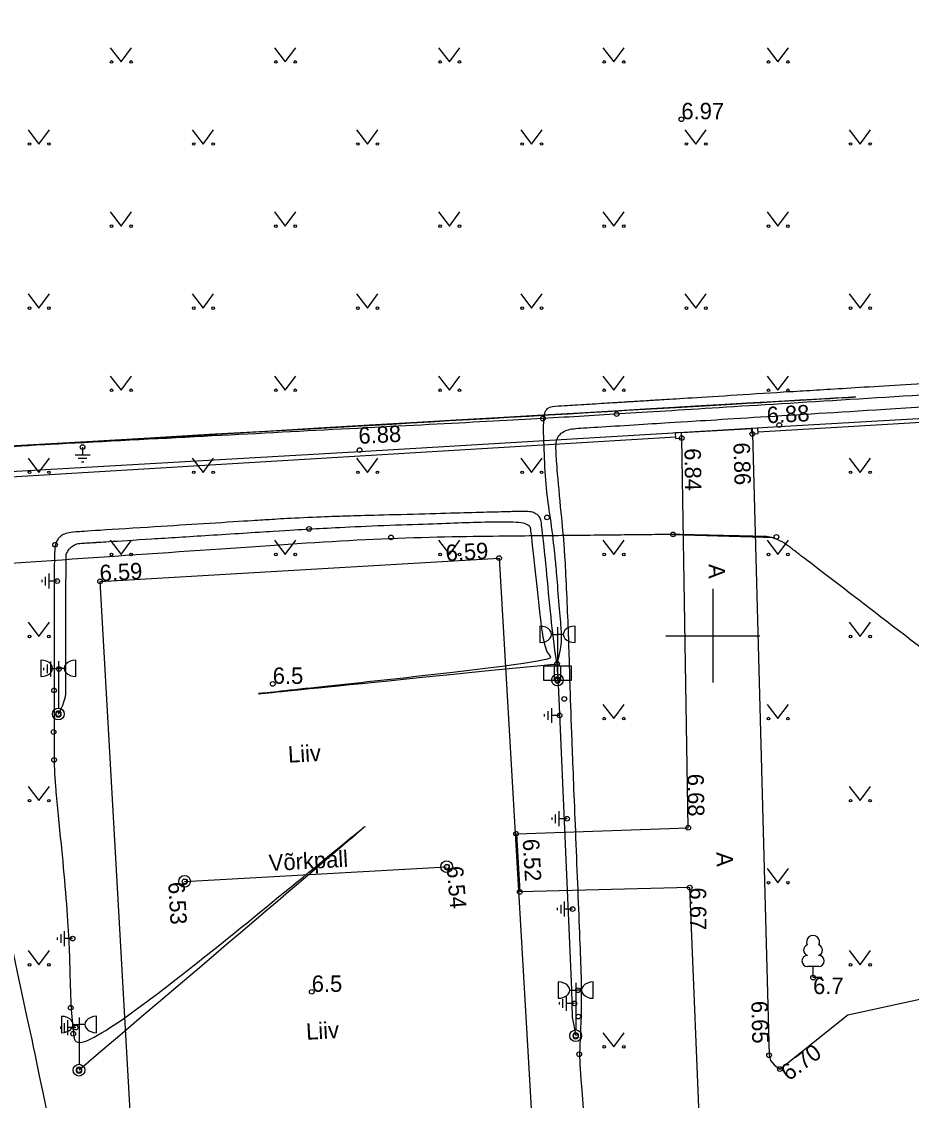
# Model space of a CAD drawing. Extents: x 473307 to 473719, y 6532843 to 6533381.
# Drawn here: x 473420.53 to 473458.46, y 6533180.18 to 6533226.19 of the extents above; entities that cross this region are included whole.
import ezdxf

# ---------------------------------------------------------------- set-up
doc = ezdxf.new("R2010")
doc.units = 0
for name, color, linetype in [('AED', 7, 'Continuous'), ('Default', 7, 'Continuous'), ('HALJASTUS', 7, 'Continuous'), ('KORGUS', 7, 'Continuous'), ('MPKAABEL', 7, 'Continuous'), ('POST', 7, 'Continuous'), ('PUU', 7, 'Continuous'), ('RAJATIS', 7, 'Continuous'), ('TEE', 7, 'Continuous'), ('VORK', 7, 'Continuous')]:
    doc.layers.add(name, color=color, linetype=linetype)

# ---------------------------------------------------------------- blocks, each defined once
blk = doc.blocks.new('VARPOS')
at = {"layer": 'Default'}
for p, q in [((-0.25, 0.25), (-0.25, -0.25)), ((-0.25, 0.25), (0.25, 0.25)), ((0.25, 0.25), (0.25, -0.25)), ((-0.25, -0.25), (0.25, -0.25))]:
    blk.add_line(p, q, dxfattribs=at)
blk = doc.blocks.new('ELKAPP')
at = {"layer": 'Default'}
for p, q in [((1.195, 0.597), (-1.195, 0.597)), ((-1.195, 0.597), (-1.195, -0.597)), ((-0.271, 0.597), (-0.271, -0.597)), ((0.271, 0.597), (0.271, -0.597)), ((1.195, -0.597), (1.195, 0.597)), ((-1.195, -0.597), (1.195, -0.597))]:
    blk.add_line(p, q, dxfattribs=at)
blk = doc.blocks.new('PRMAST')
at = {"layer": 'Default'}
for p, q in [((0, 4.5), (0, 0.5)), ((1.5, 3.193), (1.5, 4.593))]:
    blk.add_line(p, q, dxfattribs=at)
blk.add_lwpolyline([(0.5, 3.893), (0, 3.893)], dxfattribs=at)
blk.add_ellipse((1.5, 3.893), major_axis=(-1, 0), ratio=0.7, start_param=4.712389, end_param=7.853982, dxfattribs=at)
blk = doc.blocks.new('MEPOST')
at = {"layer": 'Default'}
blk.add_circle((0, 0), 0.5, dxfattribs=at)
for start, end in [(0, 180), (180, 0)]:
    blk.add_arc((0, 0), 0.25, start, end, dxfattribs=at)
blk = doc.blocks.new('MAANDU')
at = {"layer": 'Default'}
for points in [[(0, 0), (0, -0.678)], [(0.636, -0.678), (-0.636, -0.678)], [(0.368, -0.978), (-0.368, -0.978)], [(0.1, -1.278), (-0.1, -1.278)]]:
    blk.add_lwpolyline(points, dxfattribs=at)
blk = doc.blocks.new('LEHTP1')
at = {"layer": 'Default'}
for p, q in [((0.48, 0.95), (-0.48, 0.95)), ((0, 0), (0, 0.95)), ((0.76, 0), (0, 0))]:
    blk.add_line(p, q, dxfattribs=at)
for centre, radius, start, end in [((-0.34, 2.345), 0.465, 109.02174, 253.14154), ((0, 3.04), 0.554, 332.5799, 207.4201), ((0.34, 2.345), 0.465, 286.85082, 70.98591), ((-0.475, 1.425), 0.475, 90.0016, 269.3953), ((0.475, 1.425), 0.475, 270.6047, 89.9984)]:
    blk.add_arc(centre, radius, start, end, dxfattribs=at)
blk = doc.blocks.new('MURU')
at = {"layer": 'Default'}
for p, q in [((-0.927, 1.213), (0, 0)), ((0, 0), (0.891, 1.213))]:
    blk.add_line(p, q, dxfattribs=at)
for centre in [(-0.802, 0), (0.856, 0)]:
    blk.add_circle(centre, 0.11, dxfattribs=at)
blk = doc.blocks.new('VKORIS')
at = {"layer": 'Default'}
for p, q in [((0, 4), (0, -4)), ((-4, 0), (4, 0))]:
    blk.add_line(p, q, dxfattribs=at)
blk = doc.blocks.new('PLPOST')
at = {"layer": 'Default'}
blk.add_circle((0, 0), 0.5, dxfattribs=at)
blk.add_arc((0, 0), 0.25, 225, 45, dxfattribs=at)

msp = doc.modelspace()

# ---------------------------------------------------------------- linework, layer by layer
at = {"layer": 'AED'}
for points in [[(473499.831, 6533211.522), (473451.926, 6533208.685)], [(473399.054, 6533209.3), (473399.274, 6533205.529), (473448.417, 6533208.478)]]:
    msp.add_lwpolyline(points, dxfattribs=at)
at = {"layer": 'KORGUS'}
for centre in [(473448.657, 6533222.023), (473445.898, 6533209.449), (473442.754, 6533209.257), (473452.826, 6533208.98), (473448.67, 6533208.429), (473451.681, 6533208.606), (473423.132, 6533208.045), (473434.941, 6533207.916), (473442.932, 6533205.046), (473432.789, 6533204.555), (473448.301, 6533204.318), (473421.962, 6533203.88), (473436.282, 6533204.191), (473452.71, 6533204.217), (473440.889, 6533203.308), (473422.048, 6533202.329), (473423.879, 6533202.315), (473443.359, 6533198.806), (473422.122, 6533198.585), (473431.239, 6533197.948), (473443.373, 6533198.111), (473421.918, 6533197.668), (473443.664, 6533197.304), (473422.102, 6533196.661), (473443.467, 6533196.6), (473421.895, 6533195.895), (473421.918, 6533194.705), (473443.782, 6533192.197), (473448.948, 6533191.809), (473441.609, 6533191.554), (473438.652, 6533190.151), (473427.48, 6533189.525), (473441.768, 6533189.077), (473449.014, 6533189.263), (473444.019, 6533188.342), (473422.708, 6533187.085), (473454.272, 6533185.422), (473432.901, 6533184.815), (473444.252, 6533184.88), (473422.627, 6533184.136), (473444.099, 6533184.323), (473444.267, 6533183.759), (473422.845, 6533183.29), (473422.733, 6533183.026), (473444.153, 6533182.942), (473444.303, 6533182.154), (473452.397, 6533182.109), (473422.981, 6533181.474), (473422.986, 6533181.469), (473452.855, 6533181.521)]:
    msp.add_circle(centre, 0.1, dxfattribs=at)
at = {"layer": 'MPKAABEL'}
for points in [[(473448.257, 6533204.318), (473452.64, 6533204.184)], [(473443.359, 6533198.806), (473443.373, 6533198.111)], [(473443.359, 6533198.806), (473443.43, 6533197.309), (473443.98, 6533184.908), (473444.006, 6533183.735), (473444.153, 6533182.942)]]:
    msp.add_lwpolyline(points, dxfattribs=at)
for points in [[(473481.884, 6533211.687), (473479.589, 6533211.544), (473477.954, 6533211.443), (473473.664, 6533211.176), (473466.186, 6533210.711), (473462.033, 6533210.453), (473455.763, 6533210.064), (473450.004, 6533209.706), (473445.856, 6533209.448), (473442.754, 6533209.257), (473438.068, 6533209.011), (473432.416, 6533208.715), (473426.462, 6533208.402), (473419.78, 6533208.052), (473417.57, 6533207.936), (473481.884, 6533211.687), (473417.57, 6533207.936)], [(473443.359, 6533198.806), (473443.509, 6533199.309), (473443.569, 6533199.878), (473443.534, 6533200.301), (473443.423, 6533201.647), (473443.316, 6533202.942), (473443.273, 6533203.465), (473443.074, 6533205.1), (473442.881, 6533206.254), (473442.818, 6533207.734), (473442.754, 6533209.257), (473442.89, 6533209.766), (473443.409, 6533209.798), (473443.961, 6533209.832), (473444.237, 6533209.849), (473445.453, 6533209.923), (473446.212, 6533209.971), (473446.37, 6533209.981), (473446.587, 6533209.994), (473446.864, 6533210.012), (473447.231, 6533210.034), (473447.82, 6533210.071), (473448.983, 6533210.143), (473450.946, 6533210.265), (473453.353, 6533210.415), (473455.425, 6533210.544), (473459.089, 6533210.771), (473463.299, 6533211.033), (473466.711, 6533211.245), (473471.154, 6533211.521), (473474.893, 6533211.754), (473478.678, 6533211.989), (473479.288, 6533212.027), (473480.084, 6533212.076), (473481.884, 6533211.687), (473443.359, 6533198.806), (473481.884, 6533211.687)], [(473512.387, 6533012.718), (473511.709, 6533013.458), (473511.644, 6533013.813), (473511.542, 6533014.613), (473511.381, 6533017.659), (473511.142, 6533020.044), (473510.874, 6533022.048), (473510.569, 6533024.181), (473510.483, 6533025.89), (473510.516, 6533027.894), (473510.641, 6533030.331), (473510.67, 6533031.833), (473510.655, 6533032.119), (473510.649, 6533032.555), (473510.639, 6533032.762), (473510.589, 6533032.95), (473510.316, 6533033.111), (473509.354, 6533033.422), (473507.996, 6533033.86), (473502.455, 6533035.652), (473496.274, 6533037.678), (473490.95, 6533039.423), (473486.411, 6533040.598), (473481.57, 6533041.955), (473473.486, 6533044.266), (473470.456, 6533045.132), (473469.695, 6533045.349), (473468.226, 6533046.487), (473468.095, 6533047.18), (473467.821, 6533048.63), (473467.366, 6533051.035), (473466.864, 6533053.691), (473466.381, 6533056.243), (473466.321, 6533057.471), (473466.418, 6533059.213), (473466.484, 6533060.394), (473467.163, 6533064.378), (473467.581, 6533069.215), (473467.741, 6533070.834), (473467.945, 6533074.093), (473468.112, 6533076.746), (473468.308, 6533079.877), (473468.368, 6533080.827), (473468.195, 6533082.441), (473467.801, 6533084.78), (473466.975, 6533089.686), (473465.432, 6533098.846), (473464.577, 6533103.922), (473462.937, 6533114.557), (473462.089, 6533120.164), (473461.167, 6533124.352), (473460.389, 6533127.622), (473459.684, 6533130.59), (473458.638, 6533134.987), (473457.53, 6533139.179), (473456.93, 6533140.376), (473456.16, 6533141.558), (473454.075, 6533144.132), (473450.58, 6533147.98), (473447.835, 6533151.004), (473446.816, 6533152.126), (473446.343, 6533153.336), (473446.279, 6533153.709), (473445.979, 6533156.453), (473445.694, 6533158.891), (473445.318, 6533162.115), (473444.984, 6533165.254), (473444.88, 6533173.846), (473444.715, 6533176.995), (473444.365, 6533181.379), (473444.303, 6533182.154), (473444.449, 6533184.276), (473444.328, 6533187.274), (473444.133, 6533192.117), (473443.983, 6533195.824), (473443.918, 6533197.679), (473443.848, 6533200.27), (473443.685, 6533203.83), (473443.572, 6533204.805), (473443.351, 6533207.182), (473443.316, 6533207.805), (473443.288, 6533208.471), (473443.754, 6533208.817), (473444.345, 6533208.853), (473445.787, 6533208.941), (473447.513, 6533209.05), (473448.662, 6533209.121), (473453.524, 6533209.424), (473458.616, 6533209.74), (473469.92, 6533210.443), (473477.216, 6533210.896), (473479.911, 6533211.063), (473481.121, 6533211.139), (473481.696, 6533211.355), (473481.884, 6533211.687), (473512.387, 6533012.718), (473481.884, 6533211.687)], [(473557.128, 6533166.896), (473557.202, 6533167.153), (473557.17, 6533167.374), (473557.049, 6533167.727), (473556.952, 6533168.034), (473556.879, 6533168.251), (473556.724, 6533168.7), (473555.529, 6533172.103), (473554.018, 6533176.143), (473551.965, 6533180.794), (473542.001, 6533194.467), (473528.815, 6533203.479), (473521.877, 6533205.787), (473521.549, 6533205.862), (473521.332, 6533205.91), (473521.125, 6533205.955), (473520.94, 6533205.994), (473520.783, 6533206.026), (473520.617, 6533205.983), (473520.549, 6533205.81), (473520.512, 6533205.71), (473520.33, 6533205.301), (473520.277, 6533205.676), (473520.247, 6533205.87), (473520.186, 6533205.982), (473520.155, 6533206.063), (473520.032, 6533206.188), (473519.647, 6533206.25), (473519.297, 6533206.303), (473518.91, 6533206.37), (473518.338, 6533206.457), (473517.785, 6533206.534), (473517.113, 6533206.617), (473504.722, 6533206.361), (473489.125, 6533201.073), (473481.589, 6533195.708), (473477.331, 6533191.94), (473475.034, 6533189.807), (473474.489, 6533189.292), (473474.068, 6533188.932), (473473.832, 6533188.684), (473473.679, 6533188.468), (473473.566, 6533188.217), (473473.476, 6533188.304), (473473.306, 6533188.406), (473473.134, 6533188.531), (473472.969, 6533188.652), (473471.778, 6533189.567), (473469.957, 6533190.966), (473467.155, 6533193.119), (473463.064, 6533196.262), (473458.646, 6533199.657), (473454.573, 6533202.786), (473453.666, 6533203.482), (473453.293, 6533203.769), (473452.995, 6533203.998), (473452.474, 6533204.222), (473452.213, 6533204.228), (473451.967, 6533204.234), (473451.474, 6533204.245), (473450.255, 6533204.273), (473449.394, 6533204.293), (473448.978, 6533204.302), (473448.578, 6533204.312), (473448.301, 6533204.318), (473447.638, 6533204.311), (473446.313, 6533204.297), (473445.312, 6533204.286), (473443.932, 6533204.272), (473441.622, 6533204.247), (473436.282, 6533204.191), (473430.619, 6533203.804), (473423.016, 6533203.284), (473416.174, 6533202.8), (473411.7, 6533202.424), (473406.989, 6533202.027), (473406.298, 6533201.969), (473405.901, 6533201.936), (473405.663, 6533201.916), (473405.247, 6533201.618), (473405.511, 6533201.478), (473405.706, 6533201.471), (473405.859, 6533201.485), (473406.073, 6533201.505), (473406.3, 6533201.526), (473406.699, 6533201.563), (473407.182, 6533201.607), (473407.617, 6533201.647), (473410.794, 6533201.939), (473414.597, 6533202.289), (473416.16, 6533202.433), (473416.748, 6533202.487), (473416.992, 6533202.509), (473417.116, 6533202.479), (473417.282, 6533202.408), (473417.308, 6533202.242), (473417.347, 6533201.989), (473417.396, 6533201.677), (473417.449, 6533201.337), (473417.509, 6533200.949), (473418.04, 6533197.53), (473418.813, 6533192.552), (473421.708, 6533179.543), (473422.341, 6533175.512), (473423.507, 6533169.632), (473424, 6533167.141), (473424.184, 6533166.215), (473424.244, 6533165.909), (473424.294, 6533165.662), (473424.314, 6533165.561), (473424.105, 6533164.865), (473423.816, 6533164.809), (473423.525, 6533164.753), (473422.668, 6533164.588), (473418.846, 6533164.247), (473414.425, 6533164.061), (473411.47, 6533164.651), (473411.357, 6533164.673), (473410.881, 6533164.787), (473410.433, 6533164.888), (473409.953, 6533164.731), (473409.752, 6533164.287), (473409.631, 6533163.669), (473409.502, 6533157.703), (473410.074, 6533152.735), (473410.969, 6533148.729), (473415.098, 6533136.501), (473416.702, 6533131.364), (473421.711, 6533117.606), (473423.352, 6533113.701), (473430.005, 6533097.933), (473437.623, 6533088.588), (473441.02, 6533084.73), (473450.501, 6533069.242), (473457.775, 6533058.053), (473462.215, 6533052.558), (473465.73, 6533047.735), (473467.401, 6533046.054), (473469.034, 6533044.411), (473472.353, 6533043.145), (473481.411, 6533040.582), (473489.023, 6533038.632), (473491.007, 6533038.103), (473491.686, 6533037.936), (473492.014, 6533037.852), (473492.476, 6533037.76), (473492.806, 6533038.095), (473492.829, 6533038.485), (473492.856, 6533039.18), (473492.795, 6533042.335), (473492.716, 6533044.024), (473492.683, 6533044.743), (473492.671, 6533044.987), (473492.823, 6533045.601), (473492.984, 6533045.289), (473492.985, 6533045.105), (473493.028, 6533044.585), (473493.105, 6533042.767), (473493.222, 6533039.506), (473493.206, 6533038.15), (473493.196, 6533038.01), (473493.2, 6533037.815), (473493.516, 6533037.437), (473493.94, 6533037.314), (473494.338, 6533037.204), (473496.451, 6533036.58), (473497.497, 6533036.067), (473498.11, 6533035.695), (473498.481, 6533035.454), (473498.784, 6533035.294), (473499.155, 6533035.524), (473499.568, 6533035.786), (473499.965, 6533035.642), (473500.381, 6533035.468), (473500.664, 6533035.366), (473501.255, 6533035.156), (473502.131, 6533034.826), (473503.015, 6533034.496), (473504.909, 6533033.785), (473507.281, 6533033.099), (473509.703, 6533032.392), (473510.465, 6533032.171), (473510.886, 6533032.05), (473511.297, 6533031.932), (473511.665, 6533031.668), (473511.711, 6533031.312), (473511.692, 6533030.835), (473511.632, 6533029.982), (473511.533, 6533028.937), (473511.486, 6533028.283), (473511.407, 6533027.141), (473511.358, 6533026.503), (473511.358, 6533025.257), (473511.617, 6533023.934), (473511.536, 6533023.5), (473511.414, 6533022.901), (473511.43, 6533022.205), (473511.677, 6533020.728), (473511.888, 6533019.916), (473512.37, 6533017.914), (473512.52, 6533015.831), (473512.626, 6533013.709), (473512.595, 6533013.242), (473512.387, 6533012.718), (473557.128, 6533166.896), (473512.387, 6533012.718)], [(473443.359, 6533198.806), (473443.22, 6533199.671), (473443.107, 6533200.624), (473442.891, 6533203.032), (473442.743, 6533204.292), (473442.698, 6533204.78), (473442.664, 6533204.973), (473442.573, 6533205.121), (473442.436, 6533205.212), (473442.277, 6533205.291), (473441.948, 6533205.305), (473441.459, 6533205.292), (473440.868, 6533205.276), (473439.62, 6533205.242), (473438.062, 6533205.199), (473435.864, 6533205.139), (473434.409, 6533205.099), (473433.808, 6533205.083), (473432.067, 6533205.01), (473431.021, 6533204.944), (473430.454, 6533204.908), (473428.235, 6533204.768), (473426.35, 6533204.649), (473423.551, 6533204.473), (473422.778, 6533204.424), (473422.456, 6533204.377), (473422.252, 6533204.293), (473422.125, 6533204.182), (473422.048, 6533204.072), (473421.962, 6533203.88), (473421.929, 6533203.429), (473421.927, 6533202.732), (473421.926, 6533201.747), (473421.922, 6533200.026), (473421.918, 6533197.668), (473421.918, 6533194.705), (473421.934, 6533193.882), (473422.212, 6533191.138), (473422.416, 6533189.033), (473422.552, 6533187.063), (473422.586, 6533186.01), (473422.627, 6533184.136), (473422.733, 6533183.026), (473422.981, 6533181.474), (473443.359, 6533198.806), (473422.981, 6533181.474)], [(473422.102, 6533196.661), (473422.418, 6533197.256), (473422.418, 6533197.668), (473422.419, 6533198.276), (473422.42, 6533199.018), (473422.422, 6533200.069), (473422.424, 6533200.784), (473422.426, 6533202.016), (473422.427, 6533202.727), (473422.428, 6533203.353), (473422.429, 6533203.503), (473422.562, 6533203.702), (473422.693, 6533203.82), (473422.878, 6533203.929), (473423.142, 6533203.946), (473423.409, 6533203.963), (473423.659, 6533203.978), (473423.977, 6533203.998), (473426.025, 6533204.128), (473428.391, 6533204.277), (473431.596, 6533204.48), (473432.789, 6533204.555), (473433.966, 6533204.613), (473435.972, 6533204.713), (473437.988, 6533204.771), (473439.283, 6533204.827), (473440.651, 6533204.864), (473441.554, 6533204.855), (473441.927, 6533204.827), (473442.187, 6533204.697), (473442.215, 6533204.607), (473442.234, 6533204.442), (473442.287, 6533203.958), (473442.413, 6533202.815), (473442.516, 6533201.886), (473442.648, 6533200.687), (473442.718, 6533200.126), (473442.786, 6533199.752), (473442.904, 6533199.326), (473443.032, 6533199.146), (473443.359, 6533198.806), (473422.102, 6533196.661), (473443.359, 6533198.806)]]:
    msp.add_open_spline(points, degree=3, dxfattribs=at)
at = {"layer": 'POST'}
for p, q in [((473442.623, 6533200.407), (473442.623, 6533199.707)), ((473421.352, 6533198.957), (473421.352, 6533198.257)), ((473443.403, 6533185.238), (473443.403, 6533184.538)), ((473422.231, 6533183.77), (473422.231, 6533183.07))]:
    msp.add_line(p, q, dxfattribs=at)
for points in [[(473443.123, 6533200.057), (473443.373, 6533200.057)], [(473421.852, 6533198.607), (473422.102, 6533198.607)], [(473443.903, 6533184.888), (473444.153, 6533184.888)], [(473422.731, 6533183.42), (473422.981, 6533183.42)]]:
    msp.add_lwpolyline(points, dxfattribs=at)
for centre in [(473442.623, 6533200.057), (473421.352, 6533198.607), (473443.403, 6533184.888), (473422.231, 6533183.42)]:
    msp.add_ellipse(centre, major_axis=(0.5, 0), ratio=0.7, start_param=4.712389, end_param=7.853982, dxfattribs=at)
at = {"layer": 'RAJATIS'}
msp.add_lwpolyline([(473427.48, 6533189.525), (473438.652, 6533190.151)], dxfattribs=at)
at = {"layer": 'TEE'}
msp.add_lwpolyline([(473396.254, 6533260.803), (473411.137, 6533261.686), (473430.688, 6533262.81), (473450.64, 6533263.99), (473471.14, 6533265.187), (473496.199, 6533266.651), (473497.903, 6533237.901), (473499.304, 6533214.158), (473499.292, 6533213.775), (473499.248, 6533213.313), (473499.158, 6533212.95), (473498.962, 6533212.533), (473498.665, 6533212.147), (473498.271, 6533211.83), (473497.797, 6533211.622), (473497.201, 6533211.492), (473496.826, 6533211.447), (473473.837, 6533210.118), (473452.83, 6533208.91), (473434.945, 6533207.846), (473416.821, 6533206.798), (473399.468, 6533205.756), (473398.532, 6533221.8), (473397.351, 6533241.472)], close=True, dxfattribs=at)
for points in [[(473444.972, 6533172.88), (473449.489, 6533177.804), (473449.014, 6533189.263), (473441.788, 6533189.077), (473441.644, 6533191.555), (473448.948, 6533191.809), (473448.67, 6533208.429), (473448.656, 6533208.662), (473451.667, 6533208.841), (473451.681, 6533208.606), (473452.397, 6533182.109), (473452.46, 6533181.882), (473452.619, 6533181.683), (473452.855, 6533181.521), (473455.745, 6533183.836), (473474.087, 6533187.833)], [(473423.879, 6533202.315), (473440.889, 6533203.308), (473442.399, 6533177.392), (473425.34, 6533176.463), (473423.879, 6533202.315)]]:
    msp.add_lwpolyline(points, dxfattribs=at)

# ---------------------------------------------------------------- block references
at = {"layer": 'AED', "xscale": 0.5, "yscale": 0.5000000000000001, "rotation": 93.41886921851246}
for p in [(473448.538, 6533208.547), (473448.538, 6533208.547), (473451.798, 6533208.738), (473451.798, 6533208.738)]:
    msp.add_blockref('VARPOS', p, dxfattribs=at)
at = {"layer": 'HALJASTUS', "xscale": 0.5, "yscale": 0.5}
for p in [(473424.771, 6533224.467), (473431.771, 6533224.467), (473438.771, 6533224.467), (473445.771, 6533224.467), (473452.771, 6533224.467), (473421.271, 6533220.967), (473428.271, 6533220.967), (473435.271, 6533220.967), (473442.271, 6533220.967), (473449.271, 6533220.967), (473456.271, 6533220.967), (473424.771, 6533217.467), (473431.771, 6533217.467), (473438.771, 6533217.467), (473445.771, 6533217.467), (473452.771, 6533217.467), (473421.271, 6533213.967), (473428.271, 6533213.967), (473435.271, 6533213.967), (473442.271, 6533213.967), (473449.271, 6533213.967), (473456.271, 6533213.967), (473424.771, 6533210.467), (473431.771, 6533210.467), (473438.771, 6533210.467), (473445.771, 6533210.467), (473452.771, 6533210.467), (473421.271, 6533206.967), (473428.271, 6533206.967), (473435.271, 6533206.967), (473442.271, 6533206.967), (473456.271, 6533206.967), (473424.771, 6533203.467), (473431.771, 6533203.467), (473438.771, 6533203.467), (473445.771, 6533203.467), (473452.771, 6533203.467), (473421.271, 6533199.967), (473456.271, 6533199.967), (473445.771, 6533196.467), (473452.771, 6533196.467), (473421.271, 6533192.967), (473456.271, 6533192.967), (473452.771, 6533189.467), (473421.271, 6533185.967), (473456.271, 6533185.967), (473445.771, 6533182.467)]:
    msp.add_blockref('MURU', p, dxfattribs=at)
at = {"layer": 'MPKAABEL', "xscale": 0.5, "yscale": 0.5}
msp.add_blockref('MAANDU', (473423.132, 6533208.045), dxfattribs=at)
at = {"layer": 'MPKAABEL', "xscale": 0.5, "yscale": 0.5, "rotation": -90.00000000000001}
for p in [(473422.048, 6533202.329), (473422.122, 6533198.585), (473443.467, 6533196.6), (473443.782, 6533192.197), (473444.019, 6533188.342), (473422.708, 6533187.085), (473444.099, 6533184.323), (473422.845, 6533183.29)]:
    msp.add_blockref('MAANDU', p, dxfattribs=at)
at = {"layer": 'POST'}
for name, p, xscale, yscale in [('PRMAST', (473443.373, 6533198.111), 0.4999999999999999, 0.4999999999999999), ('PRMAST', (473422.102, 6533196.661), 0.4999999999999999, 0.4999999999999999), ('ELKAPP', (473443.373, 6533198.409), 0.5, 0.5), ('MEPOST', (473443.373, 6533198.111), 0.4999999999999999, 0.4999999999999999), ('MEPOST', (473422.102, 6533196.661), 0.4999999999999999, 0.4999999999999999), ('PRMAST', (473444.153, 6533182.942), 0.4999999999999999, 0.4999999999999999), ('PRMAST', (473422.981, 6533181.474), 0.4999999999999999, 0.4999999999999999), ('MEPOST', (473444.153, 6533182.942), 0.4999999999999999, 0.4999999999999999), ('MEPOST', (473422.981, 6533181.474), 0.4999999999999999, 0.4999999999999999)]:
    msp.add_blockref(name, p, dxfattribs=dict(at, xscale=xscale, yscale=yscale))
at = {"layer": 'PUU', "xscale": 0.5, "yscale": 0.5}
msp.add_blockref('LEHTP1', (473454.27, 6533185.42), dxfattribs=at)
at = {"layer": 'RAJATIS', "xscale": 0.5, "yscale": 0.5}
for p in [(473438.652, 6533190.151), (473427.48, 6533189.525)]:
    msp.add_blockref('PLPOST', p, dxfattribs=at)
at = {"layer": 'VORK', "xscale": 0.5, "yscale": 0.5}
msp.add_blockref('VKORIS', (473450, 6533200), dxfattribs=at)

# ---------------------------------------------------------------- texts
at = {"layer": 'KORGUS'}
for s, p in [('6.97', (473448.657, 6533222.023)), ('6.5', (473431.239, 6533197.948)), ('6.5', (473432.901, 6533184.815)), ('6.7', (473454.27, 6533184.72))]:
    msp.add_text(s, height=0.7, dxfattribs=at).set_placement(p)
for s, rotation, p in [('6.88', 3, (473452.313, 6533209.057)), ('6.88', 3, (473434.909, 6533208.178)), ('6.86', 271.5485, (473450.875, 6533208.233)), ('6.84', 270.9565, (473448.786, 6533207.99)), ('6.59', 3.341, (473438.626, 6533203.176)), ('6.59', 3.341, (473423.879, 6533202.315)), ('6.68', 270.9565, (473448.909, 6533194.108)), ('6.52', 273.3336, (473441.89, 6533191.32)), ('6.54', 274.7162, (473438.652, 6533190.151)), ('6.53', 273.3469, (473426.781, 6533189.484)), ('6.67', 270.3592, (473449.014, 6533189.263)), ('6.65', 271.5485, (473451.634, 6533184.422)), ('6.70', 36.974, (473453.236, 6533180.988))]:
    msp.add_text(s, height=0.7, rotation=rotation, dxfattribs=at).set_placement(p)
at = {"layer": 'TEE'}
for s, rotation, p in [('A', 270.9565, (473449.816, 6533203.056)), ('Liiv', 3.2071, (473431.907, 6533194.585)), ('Võrkpall', 3.2071, (473431.089, 6533189.961)), ('A', 270.9565, (473450.152, 6533190.769)), ('Liiv', 3.2071, (473432.678, 6533182.769))]:
    msp.add_text(s, height=0.7, rotation=rotation, dxfattribs=at).set_placement(p)

doc.saveas('drawing.dxf')
